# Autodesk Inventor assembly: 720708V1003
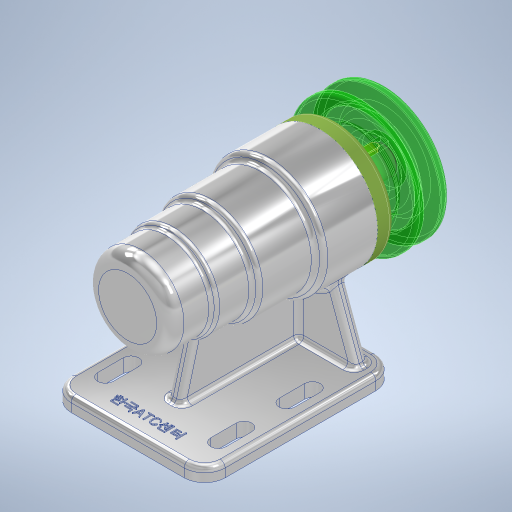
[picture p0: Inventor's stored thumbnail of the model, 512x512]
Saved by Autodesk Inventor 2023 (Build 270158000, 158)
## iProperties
Created: 2022-07
Part Number: 720708V1003
Document SubType Name: Assembly
Designer: owner
Author: owner
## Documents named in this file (12)
- C:\Users\owner\Desktop\720708V1003\720708V1003.iam
- C:\Users\owner\Desktop\720708V1003\본체.ipt
- C:\Users\owner\Desktop\720708V1003\V벨트풀리.ipt
- C:\Users\owner\Desktop\720708V1003\멈춤나사 M3.ipt
- C:\Users\owner\Desktop\720708V1003\베어링 6004.ipt
- C:\Users\owner\Desktop\720708V1003\베어링 51202.ipt
- C:\Users\owner\Desktop\720708V1003\볼트 M4.ipt
- C:\Users\owner\Desktop\720708V1003\어댑터슬리브.ipt
- C:\Users\owner\Desktop\720708V1003\오일 실 20x35x7.ipt
- C:\Users\owner\Desktop\720708V1003\축.ipt
- C:\Users\owner\Desktop\720708V1003\커버.ipt
- C:\Users\owner\Desktop\720708V1003\키 5x5.ipt
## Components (1 placed, 1 different names)
1. V벨트풀리:1 — 강체:3
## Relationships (1: WeldJoint 1)
- 강체:3 [WeldJoint]: V벨트풀리:1
